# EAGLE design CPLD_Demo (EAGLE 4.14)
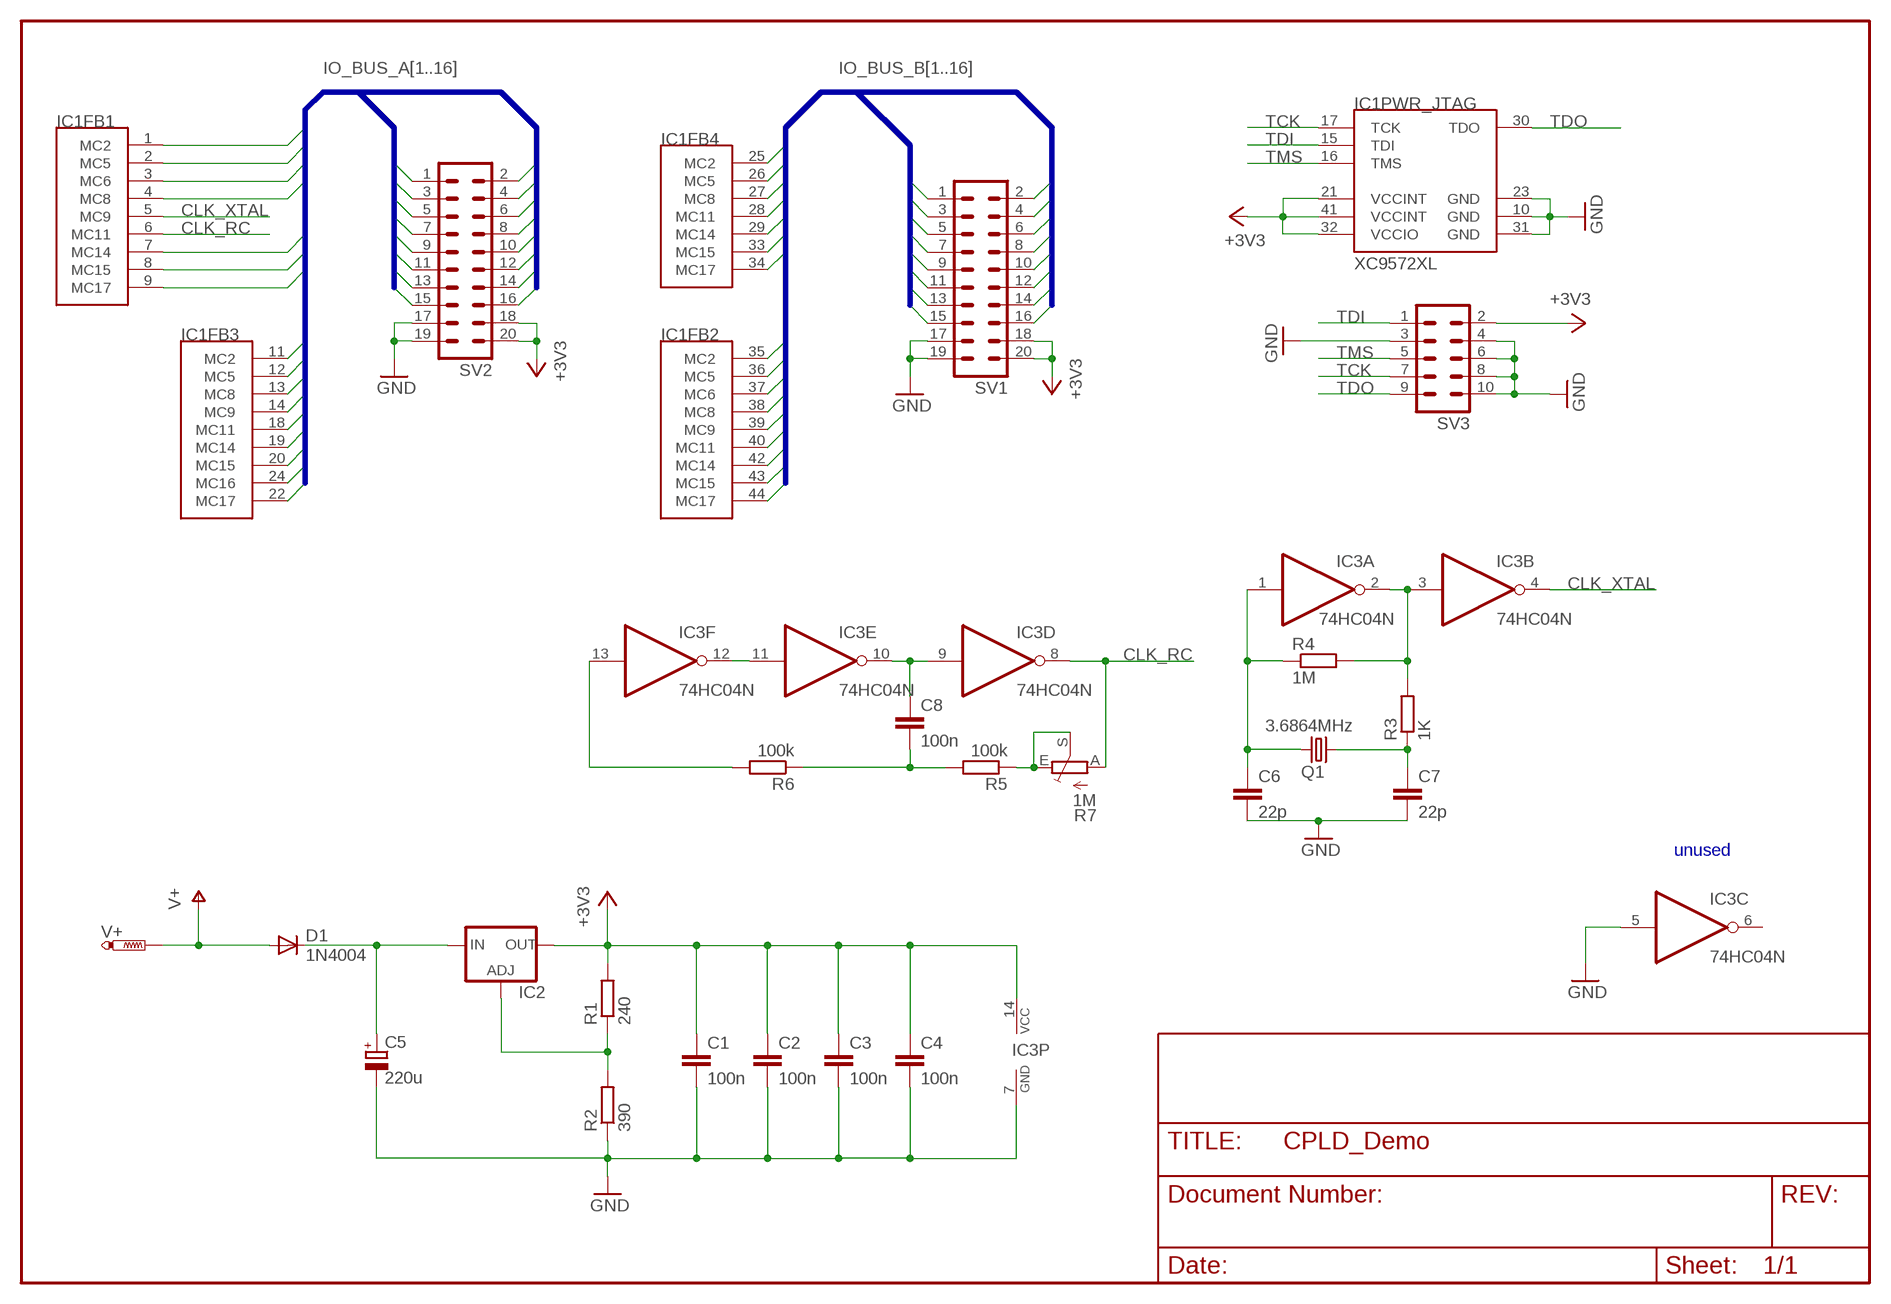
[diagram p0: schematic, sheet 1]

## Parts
C1  100n  C-EU025-024X044  [C025-024X044]
C2  100n  C-EU025-024X044  [C025-024X044]
C3  100n  C-EU025-024X044  [C025-024X044]
C4  100n  C-EU025-024X044  [C025-024X044]
C5  220u  CPOL-EUE2.5-7  [E2,5-7]
C6  22p  C-EU025-024X044  [C025-024X044]
C7  22p  C-EU025-024X044  [C025-024X044]
C8  100n  C-EU025-024X044  [C025-024X044]
D1  1N4004  [DO41-10]
IC1  XC9572XL  [PLCC44_SOCKET_TH]
IC2  LM317TL  [317TL]
IC3  74HC04N  [DIL14]
Q1  3.6864MHz  CRYTALHC49U70  [HC49U70]
R1  240  R-EU_0207/10  [0207/10]
R2  390  R-EU_0207/10  [0207/10]
R3  1K  R-EU_0207/10  [0207/10]
R4  1M  R-EU_0207/10  [0207/10]
R5  100k  R-EU_0207/10  [0207/10]
R6  100k  R-EU_0207/10  [0207/10]
R7  1M  TRIM_EU-LI15  [LI15]
SV1  MA10-2  [MA10-2]
SV2  MA10-2  [MA10-2]
SV3  ML10  [ML10]
V+  PTR1TP20SQ  [TP20SQ]

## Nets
+3V3: C1.1 C2.1 C3.1 C4.1 IC1.21(PWR_JTAG:VCCINT) IC1.32(PWR_JTAG:VCCIO) IC1.41(PWR_JTAG:VCCINT) IC2.2(OUT) IC3.14(P:VCC) R1.2 SV1.18 SV1.20 SV2.18 SV2.20 SV3.2
CLK_RC: IC1.6(FB1:MC11) IC3.8(D:O) R7.A
CLK_XTAL: IC1.5(FB1:MC9) IC3.4(B:O)
GND: C1.2 C2.2 C3.2 C4.2 C5.- C6.2 C7.2 IC1.10(PWR_JTAG:GND) IC1.23(PWR_JTAG:GND) IC1.31(PWR_JTAG:GND) IC3.5(C:I) IC3.7(P:GND) R2.1 SV1.17 SV1.19 SV2.17 SV2.19 SV3.3 SV3.4 SV3.6 SV3.8 SV3.10
IO_BUS_A1: IC1.1(FB1:MC2) SV2.1
IO_BUS_A2: IC1.2(FB1:MC5) SV2.2
IO_BUS_A3: IC1.3(FB1:MC6) SV2.3
IO_BUS_A4: IC1.4(FB1:MC8) SV2.4
IO_BUS_A5: IC1.7(FB1:MC14) SV2.5
IO_BUS_A6: IC1.8(FB1:MC15) SV2.6
IO_BUS_A7: IC1.9(FB1:MC17) SV2.7
IO_BUS_A8: IC1.11(FB3:MC2) SV2.8
IO_BUS_A9: IC1.12(FB3:MC5) SV2.9
IO_BUS_A10: IC1.13(FB3:MC8) SV2.10
IO_BUS_A11: IC1.14(FB3:MC9) SV2.11
IO_BUS_A12: IC1.18(FB3:MC11) SV2.12
IO_BUS_A13: IC1.19(FB3:MC14) SV2.13
IO_BUS_A14: IC1.20(FB3:MC15) SV2.14
IO_BUS_A15: IC1.24(FB3:MC16) SV2.15
IO_BUS_A16: IC1.22(FB3:MC17) SV2.16
IO_BUS_B1: IC1.25(FB4:MC2) SV1.1
IO_BUS_B2: IC1.26(FB4:MC5) SV1.2
IO_BUS_B3: IC1.27(FB4:MC8) SV1.3
IO_BUS_B4: IC1.28(FB4:MC11) SV1.4
IO_BUS_B5: IC1.29(FB4:MC14) SV1.5
IO_BUS_B6: IC1.33(FB4:MC15) SV1.6
IO_BUS_B7: IC1.34(FB4:MC17) SV1.7
IO_BUS_B8: IC1.35(FB2:MC2) SV1.8
IO_BUS_B9: IC1.36(FB2:MC5) SV1.9
IO_BUS_B10: IC1.37(FB2:MC6) SV1.10
IO_BUS_B11: IC1.38(FB2:MC8) SV1.11
IO_BUS_B12: IC1.39(FB2:MC9) SV1.12
IO_BUS_B13: IC1.40(FB2:MC11) SV1.13
IO_BUS_B14: IC1.42(FB2:MC14) SV1.14
IO_BUS_B15: IC1.43(FB2:MC15) SV1.15
IO_BUS_B16: IC1.44(FB2:MC17) SV1.16
N$1: C5.+ D1.C IC2.3(IN)
N$2: C7.1 Q1.2 R3.1
N$3: IC3.2(A:O) IC3.3(B:I) R3.2 R4.2
N$4: C6.1 IC3.1(A:I) Q1.1 R4.1
N$5: IC2.1(ADJ) R1.1 R2.2
N$6: IC3.11(E:I) IC3.12(F:O)
N$7: C8.1 IC3.9(D:I) IC3.10(E:O)
N$8: C8.2 R5.2 R6.1
N$9: IC3.13(F:I) R6.2
N$10: R5.1 R7.E R7.S
TCK: IC1.17(PWR_JTAG:TCK) SV3.7
TDI: IC1.15(PWR_JTAG:TDI) SV3.1
TDO: IC1.30(PWR_JTAG:TDO) SV3.9
TMS: IC1.16(PWR_JTAG:TMS) SV3.5
V+: D1.A V+.TP
Unconnected: IC3.6(C:O)

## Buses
IO_BUS_A[1..16]
IO_BUS_B[1..16]

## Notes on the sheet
- unused

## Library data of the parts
C1-C4 C6-C8 = rcl:C-EU: CAPACITOR, European symbol
C5 = rcl:CPOL-EU: POLARIZED CAPACITOR, European symbol
D1 = diode:1N4004: DIODE
IC1 = selfmade:XC9572
IC2 = v-reg:LM317TL: VOLTAGE REGULATOR
IC3 = 74xx-eu:74*04: Hex INVERTER
Q1 = crystal:CRYTAL: CRYSTAL
R1-R6 = rcl:R-EU_: RESISTOR, European symbol
R7 = pot:TRIM_EU-: POTENTIOMETER
SV1 SV2 = con-lstb:MA10-2: PIN HEADER
SV3 = con-harting-ml:ML10: HARTING
V+ = testpad:PTR1: TEST PIN

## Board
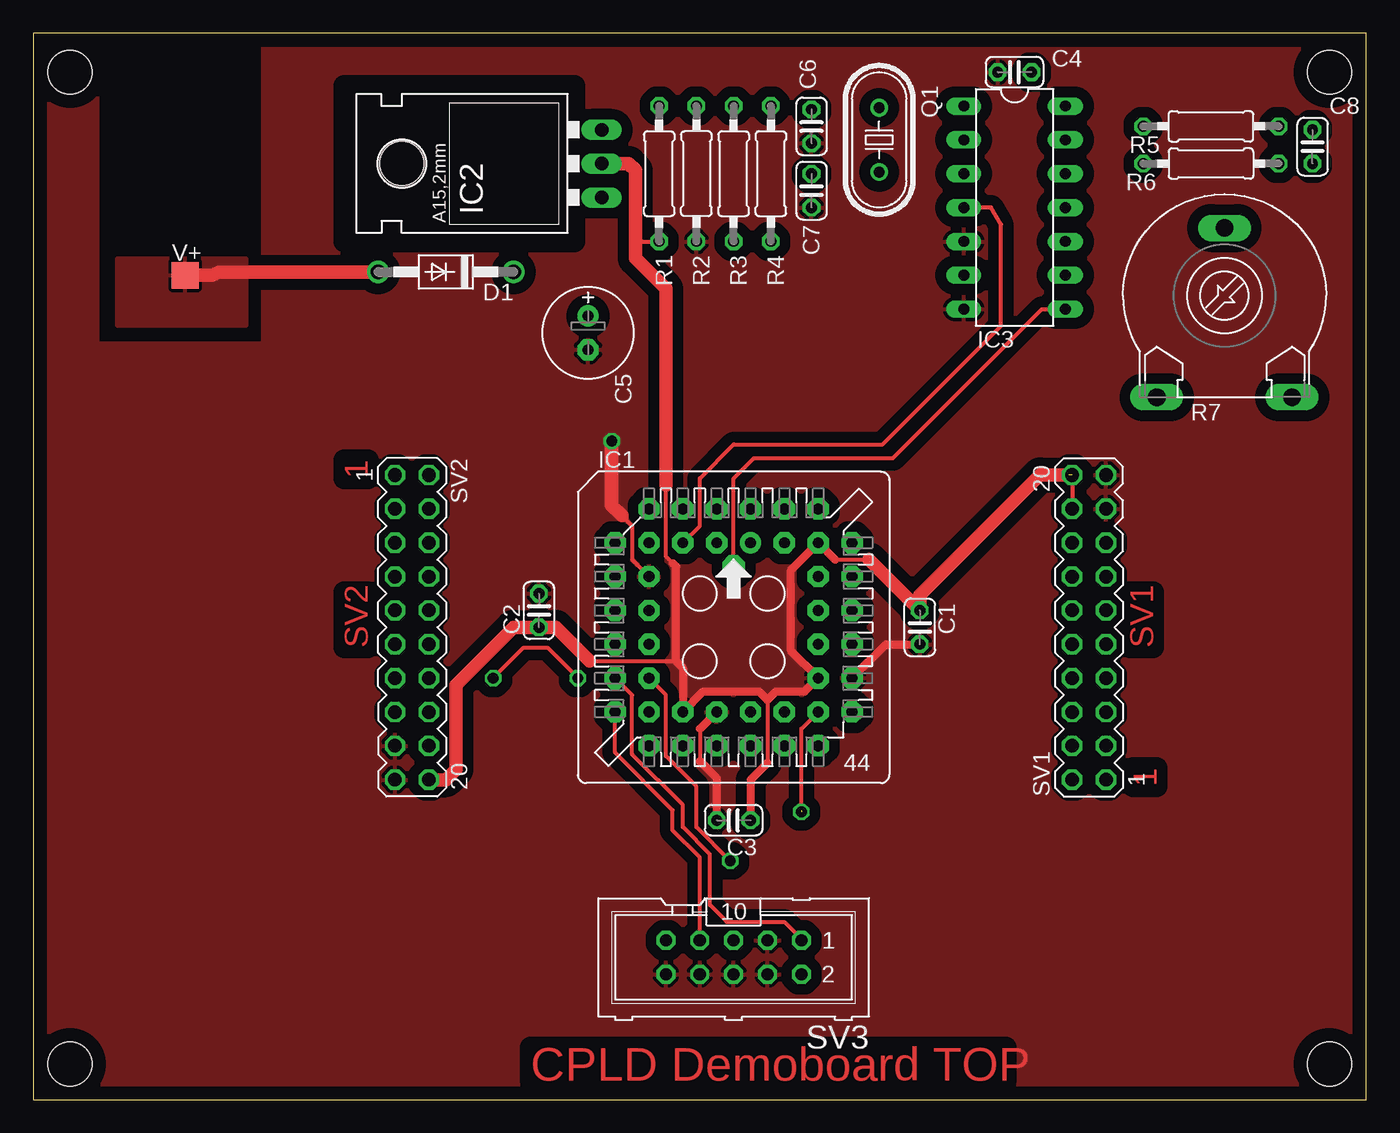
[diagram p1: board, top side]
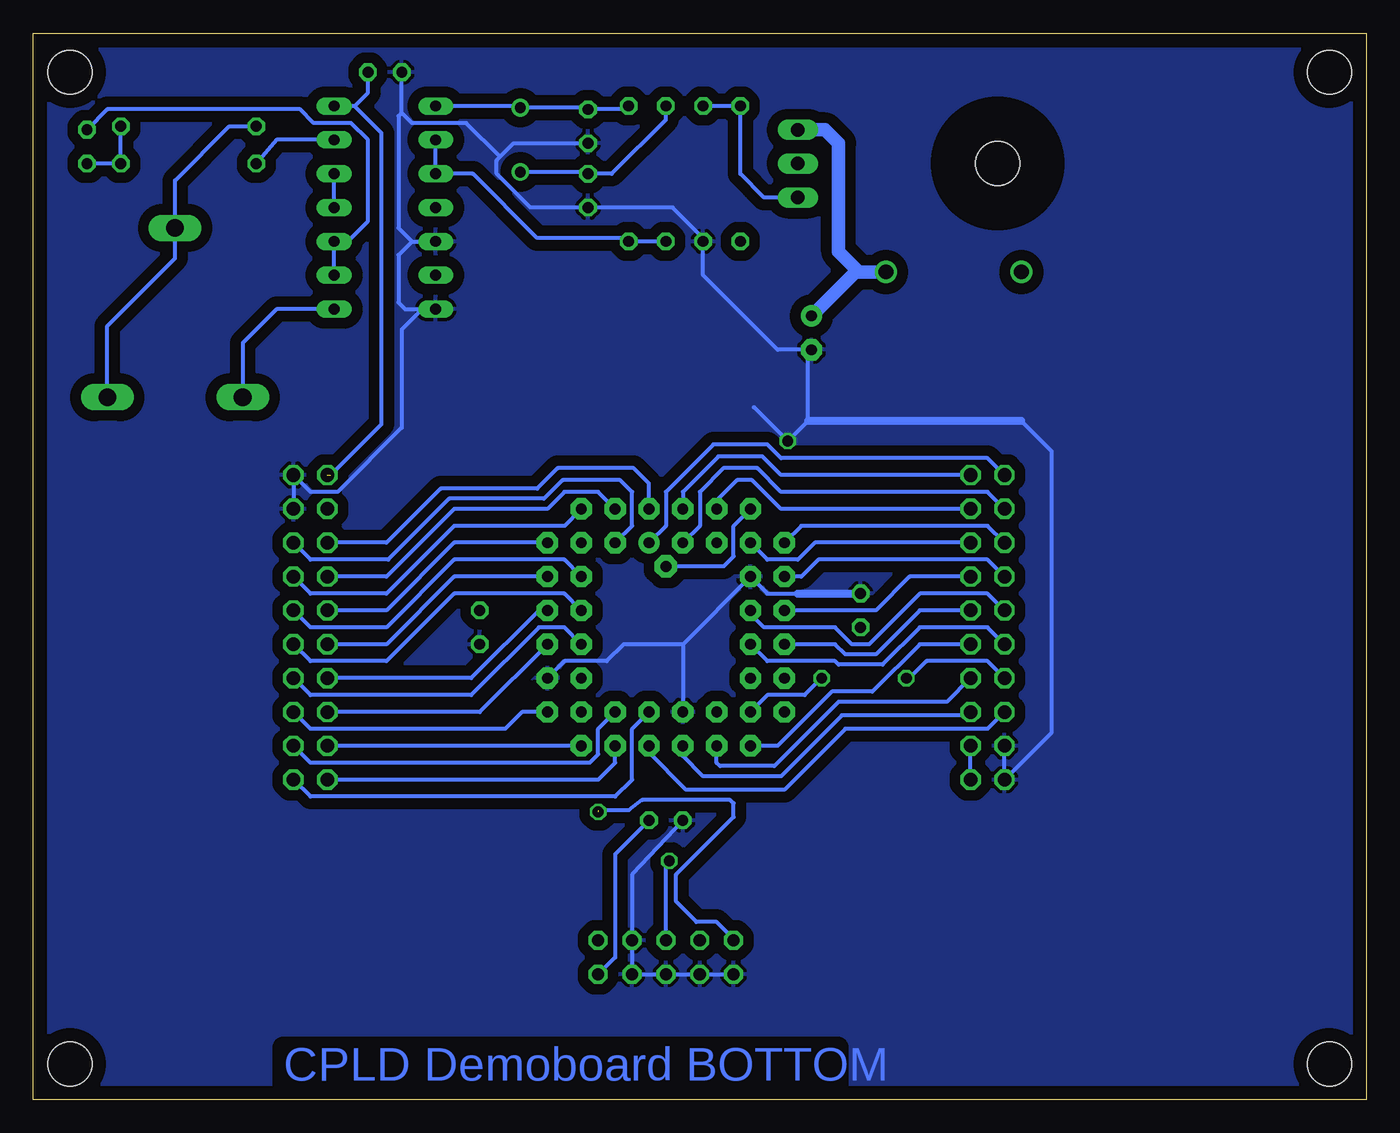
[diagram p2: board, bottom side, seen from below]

Size 100 x 80 mm. Coordinates in mm from the lower left corner, seen from the top.
Outline: 0,0 100,0 100,80 0,80 0,0
Copper layers (1*16): Top 0.035mm / dielectric 1.5mm / Bottom 0.035mm
Design rules "default": minimum track width 12mil, minimum drill 24mil, track to track 12mil, track to pad 12mil, pad to pad 12mil, via to via 12mil, smd to smd 12mil, copper to edge 40mil, drill to drill 8mil, minimum pad ring 10mil, minimum via ring 8mil, stop-mask expansion 4mil, vias tented up to drill 0mil, thermal gap 10mil
Holes 3.3 mm at 2.76,2.66 97.24,2.66 2.76,77.08 97.24,77.08
tRestrict: area 23.3,64.4 to 40.6,76.1; area 6.1,63.6 to 16.2,78.9

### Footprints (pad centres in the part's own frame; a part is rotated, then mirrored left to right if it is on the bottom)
C025-024X044 = drill 0.813 octagon: 1 -1.27,0; 2 1.27,0
E2,5-7 = drill 0.813 pad 1.6 round: + -1.27,0 | drill 0.813 pad 1.6 octagon: - 1.27,0
DO41-10 = drill 1.118 round: A 5.08,0; C -5.08,0
PLCC44_SOCKET_TH = drill 0.813 pad 1.6 round: 1 1.27,6.35 | drill 0.813 pad 1.6 octagon: 2 -1.27,8.89; 3 -1.27,6.35; 4 -3.81,8.89; 5 -3.81,6.35; 6 -6.35,8.89; 7 -8.89,6.35; 8 -6.35,6.35; 9 -8.89,3.81; 10 -6.35,3.81; 11 -8.89,1.27; 12 -6.35,1.27; 13 -8.89,-1.27; 14 -6.35,-1.27; 15 -8.89,-3.81; 16 -6.35,-3.81; 17 -8.89,-6.35; 18 -6.35,-8.89; 19 -6.35,-6.35; 20 -3.81,-8.89; 21 -3.81,-6.35; 22 -1.27,-8.89; 23 -1.27,-6.35; 24 1.27,-8.89; 25 1.27,-6.35; 26 3.81,-8.89; 27 3.81,-6.35; 28 6.35,-8.89; 29 8.89,-6.35; 30 6.35,-6.35; 31 8.89,-3.81; 32 6.35,-3.81; 33 8.89,-1.27; 34 6.35,-1.27; 35 8.89,1.27; 36 6.35,1.27; 37 8.89,3.81; 38 6.35,3.81; 39 8.89,6.35; 40 6.35,8.89; 41 6.35,6.35; 42 3.81,8.89; 43 3.81,6.35; 44 1.27,8.89
317TL = drill 1.016 long: 1 -2.54,-3.81; 2 0,-3.81; 3 2.54,-3.81 | hole 3.302: 0,11.176
DIL14 = drill 0.813 long: 1 -7.62,-3.81; 2 -5.08,-3.81; 3 -2.54,-3.81; 4 0,-3.81; 5 2.54,-3.81; 6 5.08,-3.81; 7 7.62,-3.81; 8 7.62,3.81; 9 5.08,3.81; 10 2.54,3.81; 11 0,3.81; 12 -2.54,3.81; 13 -5.08,3.81; 14 -7.62,3.81
HC49U70 = drill 0.813 round: 1 -2.413,0; 2 2.413,0
0207/10 = drill 0.813 octagon: 1 -5.08,0; 2 5.08,0
LI15 = drill 1.321 long: A -5.08,-7.62; E 5.08,-7.62; S 0,5.08
MA10-2 = drill 1.016 octagon: 1 -11.43,-1.27; 2 -11.43,1.27; 3 -8.89,-1.27; 4 -8.89,1.27; 5 -6.35,-1.27; 6 -6.35,1.27; 7 -3.81,-1.27; 8 -3.81,1.27; 9 -1.27,-1.27; 10 -1.27,1.27; 11 1.27,-1.27; 12 1.27,1.27; 13 3.81,-1.27; 14 3.81,1.27; 15 6.35,-1.27; 16 6.35,1.27; 17 8.89,-1.27; 18 8.89,1.27; 19 11.43,-1.27; 20 11.43,1.27
ML10 = drill 0.914 octagon: 1 -5.08,-1.27; 2 -5.08,1.27; 3 -2.54,-1.27; 4 -2.54,1.27; 5 0,-1.27; 6 0,1.27; 7 2.54,-1.27; 8 2.54,1.27; 9 5.08,-1.27; 10 5.08,1.27
TP20SQ = smd 2 x 2: TP 0,0

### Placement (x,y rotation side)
C1  66.51,35.43 270 top
C2  37.94,36.7 90 top
C3  52.54,20.95 180 top
C4  73.62,77.08 180 top
C5  41.62,57.53 270 top
C6  58.38,73.02 270 top
C7  58.38,68.19 270 top
C8  95.97,71.5 270 top
D1  30.95,62.1 180 top
IC1  52.54,35.43 0 top
IC2  38.82,70.23 90 top
IC3  73.62,66.92 270 top
Q1  63.46,72 270 top
R1  46.95,69.46 270 top
R2  49.75,69.46 90 top
R3  52.54,69.46 270 top
R4  55.33,69.46 270 top
R5  88.35,73.02 0 top
R6  88.35,70.23 180 top
R7  89.37,60.32 0 top
SV1  79.21,35.43 90 top
SV2  28.41,35.43 270 top
SV3  52.54,10.66 180 top
V+  11.39,61.84 0 top

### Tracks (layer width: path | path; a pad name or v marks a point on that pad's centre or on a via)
+3V3  (1 unrouted)
  Top 0.305: 41.74,32.89 48.22,32.89 | 60.16,40.51 62.7,40.51 | 55.08,29.97 55.08,25.27 | 47.97,40.25 47.46,40.76 47.46,46.1 | SV1.20 SV1.18 | 46.95,64.64 47.21,64.38 R1.2 45.68,64.38 45.43,64.13 45.17,64.13
  Top 0.61: 60.16,40.51 IC1.41 56.86,39.75 56.86,33.65 IC1.32 57.87,30.6 55.71,30.6 55.08,29.97 54.45,30.6 50.25,30.6 IC1.21 48.73,32.38 48.22,32.89 48.22,40 47.97,40.25 | C3.1 53.81,24 55.08,25.27
  Top 1.016: 41.74,32.89 39.2,35.43 C2.1 36.03,35.43 31.71,31.11 31.71,24.76 30.95,24 SV2.20 | 62.7,40.51 C1.1 66.51,37.84 75.53,46.86 SV1.20 | IC2.2 44.67,70.23 45.17,69.72 45.17,64.13 45.17,63.11 47.46,60.83 47.46,46.1
  Bottom 0.305: C3.1 56.35,18.41 56.35,10.66 SV3.2 | 75.91,74.54 IC3.14 | 75.91,74.54 73.88,72.51 73.88,50.67 77.69,46.86 | 75.91,74.54 74.89,75.56 C4.1 | SV2.20 SV2.18
  pour Top (isolate 0.813): 47.21,30.09 47.21,41.27 57.87,41.27 57.87,30.09
CLK_RC  (via drill 0.81 pad 1.68)
  Top 0.305: IC3.8 75.65,59.3 64.48,48.13 54.06,48.13 52.54,46.6 v52.54,40
  Bottom 0.305: IC1.6 47.46,43.05 47.46,40.76 48.22,40 v52.54,40 | IC3.8 81.75,59.3 84.29,56.76 R7.A
CLK_XTAL
  Top 0.305: IC1.5 50,43.05 50,46.6 52.54,49.14 63.72,49.14 72.61,58.03 72.61,65.65 71.84,66.92 IC3.4
GND  (via drill 0.81)
  Top 0.305: 50,27.81 50,25.39 | 44.16,43.81 44.92,43.05 44.92,40.51 IC1.10
  Top 0.61: IC1.31 63.97,34.16 C1.2 | IC1.23 50,27.81 | 50,25.39 51.27,24.12 C3.2
  Top 1.016: v43.4,49.4 43.4,44.57 44.16,43.81
  Bottom 0.305: 51.27,34.16 IC1.23 | 51.27,34.16 IC1.10 44.92,37.97 42.63,37.97 | 51.27,34.16 55.71,34.16 56.98,32.89 60.16,32.89 IC1.31 | C3.2 55.08,16.89 SV3.3 SV3.4 SV3.6 SV3.8 SV3.10 | 25.87,50.92 23.58,48.64 23.58,27.55 SV2.19 SV2.17 | 71.59,64.38 72.61,63.37 72.61,59.81 72.1,59.3 IC3.7 | IC3.7 70.07,59.3 | IC3.7 70.83,59.3 72.35,57.78 72.35,50.41 77.18,45.59 79.21,45.59 SV1.19 SV1.17 | 64.99,70.73 65.24,70.48 65.24,69.46 62.7,66.92 C7.2 52.03,66.92 49.75,64.64 R2.1 49.75,61.84 44.16,56.26 C5.- 41.62,56 41.87,55.75 41.87,50.92 v43.4,49.4 45.94,51.94 | 64.99,70.73 63.97,71.75 C6.2 | 72.35,74.04 C4.2 | 72.35,74.04 71.59,73.27 67.53,73.27 64.99,70.73 | 71.59,64.38 IC3.5 | 71.59,64.38 72.61,65.4 72.61,73.78 72.35,74.04
  Bottom 0.61: 42.63,37.97 C2.2 | 25.87,50.92 41.87,50.92
  pour Bottom (isolate 0.813): 0.47,0.63 0.47,79.37 99.28,79.37 99.28,0.63
  pour Top (isolate 0.813): 0.22,0.63 0.22,79.37 4.79,79.37 4.79,56.76 17.23,56.76 17.23,79.37 99.28,79.37 99.28,0.63
IO_BUS_A1
  Bottom 0.305: SV2.1 28.41,48.13 43.9,48.13 44.92,49.14 48.98,49.14 52.54,45.59 52.54,43.05 IC1.1
IO_BUS_A2
  Bottom 0.305: SV2.2 43.9,46.86 45.3,48.26 48.6,48.26 51.27,45.59 IC1.2
IO_BUS_A3
  Bottom 0.305: SV2.3 28.41,45.59 43.9,45.59 45.68,47.37 48.22,47.37 50,45.59 50,43.05 IC1.3
IO_BUS_A4
  Bottom 0.305: SV2.4 43.9,44.32 46.06,46.48 47.21,46.48 48.73,44.95 IC1.4
IO_BUS_A5
  Bottom 0.305: SV2.5 28.41,43.05 42.38,43.05 IC1.7
IO_BUS_A6
  Bottom 0.305: SV2.6 41.36,41.78 42.63,40.51 44.92,40.51 IC1.8
IO_BUS_A7
  Bottom 0.305: SV2.7 28.41,40.51 41.11,40.51 42.38,39.24 IC1.9
IO_BUS_A8
  Bottom 0.305: SV2.8 34.25,39.24 36.79,36.7 IC1.11
IO_BUS_A9
  Bottom 0.305: SV2.9 28.41,37.97 33.49,37.97 37.3,34.16 38.57,34.16 39.84,35.43 45.17,35.43 46.19,36.44 IC1.12
IO_BUS_A10
  Bottom 0.305: SV2.10 33.49,36.7 36.79,33.4 39.08,33.4 39.84,34.16 IC1.13
IO_BUS_A11
  Bottom 0.305: IC1.14 44.92,32.89 39.84,32.89 39.59,32.63 36.28,32.63 33.49,35.43 28.41,35.43 SV2.11
IO_BUS_A12
  Bottom 0.305: SV2.12 33.49,34.16 37.05,30.6 40.09,30.6 44.16,26.54 IC1.18
IO_BUS_A13  (via drill 0.81)
  Top 0.305: v34.51,31.62 36.79,33.9 38.57,33.9 v40.86,31.62
  Bottom 0.305: SV2.13 28.41,32.89 32.98,32.89 34.25,31.62 v34.51,31.62 | IC1.19 44.92,30.35 42.13,30.35 v40.86,31.62
IO_BUS_A14
  Bottom 0.305: SV2.14 31.46,29.84 39.59,29.84 44.41,25.01 48.48,25.01 48.73,25.27 IC1.20
IO_BUS_A15
  Bottom 0.305: IC1.24 53.81,26.03 51.02,23.24 43.65,23.24 39.08,27.81 28.41,27.81 SV2.15
IO_BUS_A16
  Bottom 0.305: IC1.22 51.27,25.78 49.75,24.25 43.9,24.25 39.33,28.82 29.93,28.82 SV2.16
IO_BUS_B1
  Bottom 0.305: IC1.25 55.08,27.81 55.08,24 56.35,22.73 79.21,22.73 SV1.1
IO_BUS_B2
  Bottom 0.305: SV1.2 57.62,24 56.35,25.27 IC1.26
IO_BUS_B3
  Bottom 0.305: SV1.3 79.21,25.27 58.25,25.27 57.62,25.9 57.62,27.81 IC1.27
IO_BUS_B4
  Bottom 0.305: IC1.28 SV1.4
IO_BUS_B5
  Bottom 0.305: IC1.29 63.34,29.08 64.61,27.81 79.21,27.81 SV1.5
IO_BUS_B6
  Bottom 0.305: SV1.6 66.51,29.08 IC1.33
IO_BUS_B7
  Bottom 0.305: SV1.7 79.21,30.35 67.14,30.35 62.06,35.43 60.16,35.43 IC1.34
IO_BUS_B8
  Bottom 0.305: SV1.8 67.14,31.62 62.06,36.7 IC1.35
IO_BUS_B9
  Bottom 0.305: IC1.36 60.16,37.97 68.41,37.97 73.5,32.89 79.21,32.89 SV1.9
IO_BUS_B10
  Bottom 0.305: SV1.10 73.5,34.16 68.41,39.24 IC1.37
IO_BUS_B11
  Bottom 0.305: IC1.38 60.16,40.51 68.41,40.51 73.5,35.43 79.21,35.43 SV1.11
IO_BUS_B12
  Bottom 0.305: SV1.12 73.5,36.7 68.41,41.78 IC1.39
IO_BUS_B13
  Bottom 0.305: IC1.40 60.16,43.05 68.41,43.05 73.5,37.97 79.21,37.97 SV1.13
IO_BUS_B14
  Bottom 0.305: SV1.14 73.5,39.24 68.41,44.32 61.43,44.32 60.16,45.59 57.62,45.59 IC1.42
IO_BUS_B15
  Bottom 0.305: IC1.43 55.08,43.05 55.08,45.59 55.97,46.48 60.29,46.48 61.68,45.08 68.8,45.08 73.37,40.51 79.21,40.51 SV1.15
IO_BUS_B16
  Bottom 0.305: IC1.44 53.81,46.22 54.95,47.37 60.67,47.37 62.19,45.84 69.43,45.84 73.5,41.78 SV1.16
N$1
  Bottom 0.305: 38.32,62.1 38.06,62.1
  Bottom 1.016: IC2.3 40.6,72.77 39.59,71.75 39.59,63.62 38.06,62.1 D1.C | C5.+ 38.32,62.1
N$2
  Bottom 0.305: Q1.2 58.51,69.59 C7.1 56.6,69.46 52.54,73.53 R3.1
N$3
  Bottom 0.305: IC3.2 IC3.3 67.02,69.46 62.19,64.64 55.59,64.64 R4.2 R3.2
N$4
  Bottom 0.305: IC3.1 63.46,74.54 Q1.1 58.51,74.42 C6.1 55.59,74.29 R4.1
N$5
  Bottom 0.305: R2.2 47.21,74.54 46.95,74.29 R1.1 46.95,69.46 45.17,67.69 IC2.1
N$6
  Bottom 0.305: IC3.11 IC3.12
N$7
  Bottom 0.305: IC3.9 IC3.10 76.42,64.38 74.89,65.91 74.89,72 76.16,73.27 78.96,73.27 79.97,74.29 94.45,74.29 C8.1
N$8
  Bottom 0.305: R5.2 R6.1 C8.2
N$9
  Bottom 0.305: IC3.13 81.75,72 R6.2
N$10
  Bottom 0.305: R5.1 85.31,73.02 89.37,68.96 R7.S 89.37,63.11 94.45,58.03 R7.E
TCK
  Top 0.305: SV3.7 50,18.16 47.97,20.19 47.97,21.71 43.65,26.03 IC1.17
TDI
  Top 0.305: IC1.15 44.92,30.35 44.92,25.9 48.73,22.09 48.73,20.44 50.76,18.41 50.76,14.6 52.03,13.33 56.35,13.33 57.62,12.06 SV3.1
TDO  (via drill 0.81)  (1 unrouted)
  Top 0.305: IC1.30 57.62,27.81 v57.62,21.58
  Bottom 0.305: SV3.9 47.46,12.06 48.73,13.33 50.25,13.33 51.78,14.85 51.78,16.89 47.46,21.2 47.46,22.22 47.71,22.47 54.32,22.47 55.33,21.71 57.62,21.71
TMS  (via drill 0.81)
  Top 0.305: IC1.16 47.46,30.35 47.46,25.78 49.75,23.49 49.75,20.44 v52.29,17.9
  Bottom 0.305: v52.29,17.9 52.54,17.65 SV3.5
V+
  Top 1.016: D1.A 13.93,62.1 13.42,61.84 V+.TP
  pour Top: 6.31,63.11 15.96,63.11 15.96,58.03 6.31,58.03

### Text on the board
Top: 1 | SV2 | SV1 | 1 | CPLD Demoboard TOP
Bottom: CPLD Demoboard BOTTOM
